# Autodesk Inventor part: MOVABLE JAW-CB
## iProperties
Created: 2006-07
Part Number: MOVABLE JAW-CB
Material: Cast Iron
Document SubType Name: Modeling
Designer: rollin42
Density: 7.25 g/cm^3
Stock Number: MOVABLE JAW-CB
Author: rollin42
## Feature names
1. Extrusion1
2. Extrusion2
3. Extrusion3
4. Fillet1
5. Fillet2
6. Hole1
7. Hole2
8. Hole3
9. Rectangular Pattern1
10. Fillet3
